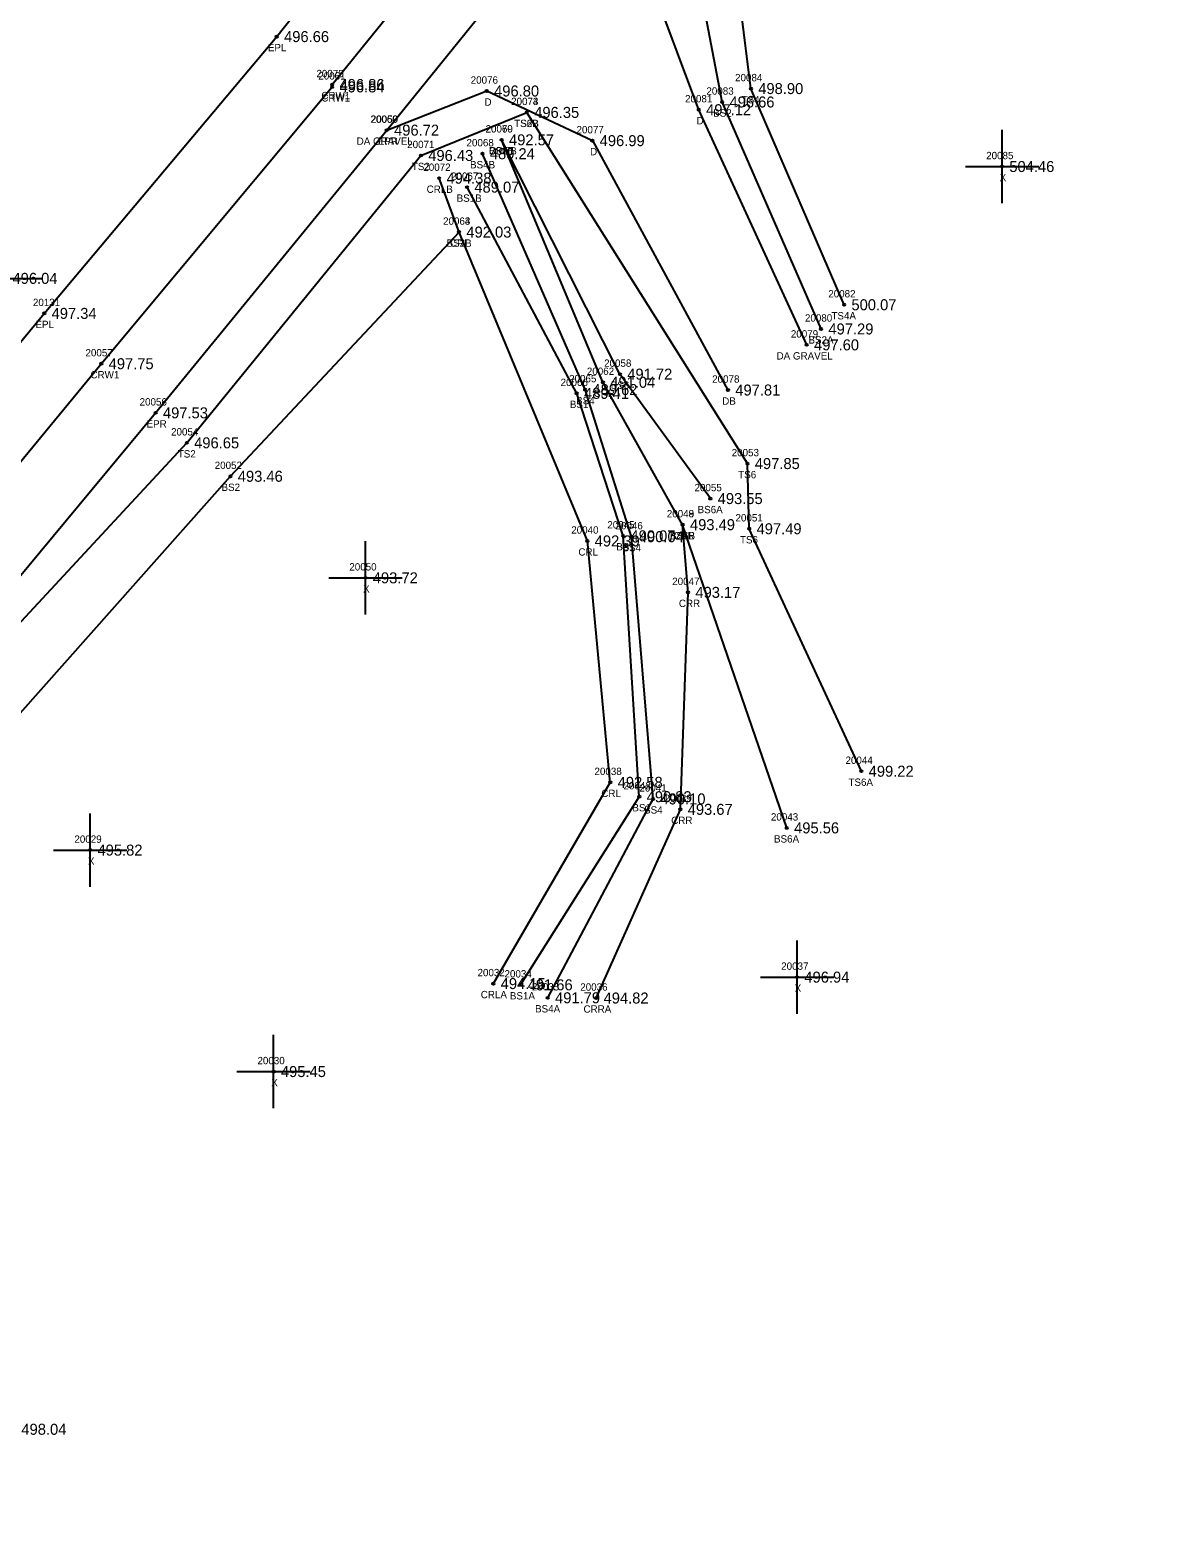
# Model space of a CAD drawing. Extents: x 1649406 to 1650436, y 896752 to 898178.
# Drawn here: x 1649581.2 to 1649733.9, y 896790.3 to 896995.9 of the extents above; entities that cross this region are included whole.
import ezdxf

# ---------------------------------------------------------------- set-up
doc = ezdxf.new("R2010")
doc.units = 0
for name, color, linetype in [('RD_DTM_BkLn1', 7, 'Continuous'), ('RD_DTM_BkLn2', 7, 'Continuous'), ('RD_DTM_BkLn_txCode', 7, 'Continuous'), ('RD_EX_Driveway', 7, 'Continuous'), ('RD_EX_Driveway_txCode', 7, 'Continuous'), ('RD_EX_H2O', 7, 'Continuous'), ('RD_EX_H2O_txCode', 7, 'Continuous'), ('RD_EX_Misc', 7, 'Continuous'), ('RD_EX_Misc_txCode', 7, 'Continuous'), ('RD_EX_Road', 7, 'Continuous'), ('RD_EX_Road_txCode', 7, 'Continuous'), ('RD_EX_TX_Driveway_ELEV', 7, 'Continuous'), ('RD_EX_TX_H2O_ELEV', 7, 'Continuous'), ('RD_EX_TX_Misc_ELEV', 7, 'Continuous'), ('RD_EX_TX_Road_ELEV', 7, 'Continuous'), ('RD_HC_Survey_ELEV', 7, 'Continuous'), ('RD_HC_Survey_txCode', 7, 'Continuous'), ('RD_SMD_Locator', 7, 'Continuous')]:
    doc.layers.add(name, color=color, linetype=linetype)

msp = doc.modelspace()

# ---------------------------------------------------------------- linework, layer by layer
at = {"layer": 'RD_DTM_BkLn1'}
msp.add_lwpolyline([(1649466.79, 896799.14), (1649494.97, 896834.25), (1649557.53, 896909.97), (1649590.88, 896950.41), (1649622.36, 896988.16), (1649622.36, 896988.48), (1649654.33, 897027.92), (1649685.38, 897067.52), (1649715.96, 897107.48), (1649743.64, 897146.32), (1649771.01, 897187.23), (1649797.64, 897230.08), (1649820.89, 897273.98), (1649842.91, 897321.22), (1649862.74, 897368.05), (1649877.08, 897408.66)], dxfattribs=at)
at = {"layer": 'RD_DTM_BkLn2'}
msp.add_line((1649684.35, 896887.11), (1649670.15, 896928.46), dxfattribs=at)
for points in [[(1649689.03, 896955.15), (1649675.54, 896986.1), (1649671.09, 897009.54), (1649678.93, 897030.09), (1649699.37, 897056.41), (1649730.7, 897097.01), (1649758.94, 897137.57), (1649785.6, 897178.21), (1649814.8, 897219.5), (1649846.42, 897264.34)], [(1649692.17, 896958.45), (1649679.46, 896987.93), (1649676.76, 897009.49), (1649682.34, 897025.02), (1649708.77, 897048.86), (1649742.68, 897086.45), (1649767.3, 897132.79), (1649789.94, 897176.61), (1649819.17, 897217.64), (1649850.28, 897262.86)], [(1649477.28, 896790.29), (1649506.04, 896824.84), (1649536.41, 896861.97), (1649567.77, 896902.18), (1649602.54, 896939.62), (1649634.46, 896978.81), (1649648.91, 896984.68)], [(1649694.52, 896894.84), (1649679.23, 896927.9), (1649678.99, 896936.79), (1649648.91, 896984.68)], [(1649673.93, 896932.02), (1649661.6, 896948.99), (1649645.47, 896980.94)], [(1649651.75, 896863.94), (1649666.13, 896891.06), (1649663.18, 896926.82), (1649656.85, 896946.88), (1649642.86, 896979.05)], [(1649648.02, 896865.71), (1649664.24, 896891.36), (1649662.04, 896926.94), (1649655.71, 896946.37), (1649640.75, 896974.49)], [(1649560.5, 896880.33), (1649573.3, 896895.47), (1649608.49, 896935.06), (1649639.66, 896968.36)]]:
    msp.add_lwpolyline(points, dxfattribs=at)
at = {"layer": 'RD_EX_Driveway'}
for points in [[(1649687.07, 896952.98), (1649672.35, 896985.05), (1649663.5, 897008.75), (1649667.92, 897029.33)], [(1649629.8, 896982.26), (1649643.44, 896987.6), (1649657.84, 896980.83), (1649676.33, 896946.82)]]:
    msp.add_lwpolyline(points, dxfattribs=at)
at = {"layer": 'RD_EX_H2O'}
for points in [[(1649658.37, 896863.91), (1649669.84, 896889.64), (1649670.89, 896919.23), (1649670.15, 896928.46), (1649659.28, 896947.88), (1649645.47, 896980.94)], [(1649644.34, 896865.88), (1649660.29, 896893.32), (1649657.16, 896926.24), (1649639.66, 896968.36), (1649636.95, 896975.71)]]:
    msp.add_lwpolyline(points, dxfattribs=at)
at = {"layer": 'RD_EX_Misc'}
for p, q in [((1649713.7, 896972.3), (1649713.7, 896982.3)), ((1649708.7, 896977.3), (1649718.7, 896977.3)), ((1649572.77, 896962.05), (1649582.77, 896962.05)), ((1649626.9, 896916.21), (1649626.9, 896926.21)), ((1649621.9, 896921.21), (1649631.9, 896921.21)), ((1649589.36, 896879.08), (1649589.36, 896889.08)), ((1649584.36, 896884.08), (1649594.36, 896884.08)), ((1649685.75, 896861.76), (1649685.75, 896871.76)), ((1649680.75, 896866.76), (1649690.75, 896866.76)), ((1649614.37, 896848.88), (1649614.37, 896858.88)), ((1649609.37, 896853.88), (1649619.37, 896853.88))]:
    msp.add_line(p, q, dxfattribs=at)
at = {"layer": 'RD_EX_Road'}
for points in [[(1649459.38, 896805.71), (1649486.55, 896839.62), (1649513.65, 896873.34), (1649538.22, 896902.56), (1649549.43, 896916.62), (1649583.1, 896957.27), (1649614.8, 896995.02), (1649647.06, 897035.69), (1649677.62, 897074.51), (1649708.33, 897114.44), (1649735.5, 897151.61), (1649762.11, 897192.19), (1649788.21, 897235.29), (1649812.17, 897279.73), (1649834.32, 897326.54), (1649852.94, 897371.82), (1649867.51, 897411.96)], [(1649474.75, 896792.65), (1649502.78, 896827.35), (1649565.2, 896903.92), (1649598.28, 896943.71), (1649629.8, 896982.26), (1649667.92, 897029.33), (1649693.13, 897061.44), (1649723.58, 897101.84), (1649752.37, 897141.09), (1649779.72, 897182.3), (1649806.12, 897225.84), (1649830.13, 897270.79), (1649852.39, 897317.43), (1649871.98, 897364.35), (1649886.55, 897406.09)]]:
    msp.add_lwpolyline(points, dxfattribs=at)
at = {"layer": 'RD_SMD_Locator'}
for centre in [(1649614.8, 896995.02), (1649622.36, 896988.48), (1649622.36, 896988.16), (1649643.44, 896987.6), (1649679.46, 896987.93), (1649648.91, 896984.68), (1649648.91, 896984.68), (1649672.35, 896985.05), (1649675.54, 896986.1), (1649629.8, 896982.26), (1649629.8, 896982.26), (1649645.47, 896980.94), (1649645.47, 896980.94), (1649657.84, 896980.83), (1649634.46, 896978.81), (1649642.86, 896979.05), (1649713.7, 896977.3), (1649636.95, 896975.71), (1649640.75, 896974.49), (1649639.66, 896968.36), (1649639.66, 896968.36), (1649692.17, 896958.45), (1649583.1, 896957.27), (1649689.03, 896955.15), (1649687.07, 896952.98), (1649590.88, 896950.41), (1649659.28, 896947.88), (1649661.6, 896948.99), (1649655.71, 896946.37), (1649656.85, 896946.88), (1649676.33, 896946.82), (1649598.28, 896943.71), (1649602.54, 896939.62), (1649608.49, 896935.06), (1649678.99, 896936.79), (1649673.93, 896932.02), (1649662.04, 896926.94), (1649663.18, 896926.82), (1649670.15, 896928.46), (1649670.15, 896928.46), (1649679.23, 896927.9), (1649657.16, 896926.24), (1649626.9, 896921.21), (1649670.89, 896919.23), (1649694.52, 896894.84), (1649660.29, 896893.32), (1649664.24, 896891.36), (1649666.13, 896891.06), (1649669.84, 896889.64), (1649684.35, 896887.11), (1649589.36, 896884.08), (1649644.34, 896865.88), (1649648.02, 896865.71), (1649685.75, 896866.76), (1649651.75, 896863.94), (1649658.37, 896863.91), (1649614.37, 896853.88)]:
    msp.add_circle(centre, 0.15, dxfattribs=at)

# ---------------------------------------------------------------- texts
at = {"layer": 'RD_DTM_BkLn_txCode'}
for s, p in [('20084', (1649677.3, 896988.93)), ('20073', (1649646.76, 896985.68)), ('20074', (1649646.76, 896985.68)), ('20083', (1649673.39, 896987.1)), ('TS4', (1649678.21, 896985.93)), ('BS2', (1649674.32, 896984.1)), ('20070', (1649643.27, 896981.94)), ('TS6B', (1649647.17, 896982.68)), ('TS2B', (1649647.2, 896982.68)), ('20071', (1649632.59, 896979.81)), ('20068', (1649640.68, 896980.05)), ('BS6B', (1649643.74, 896978.94)), ('TS2', (1649633.22, 896976.81)), ('20067', (1649638.57, 896975.49)), ('BS4B', (1649641.16, 896977.05)), ('BS1B', (1649639.33, 896972.49)), ('20063', (1649637.48, 896969.36)), ('BS2B', (1649637.96, 896966.36)), ('20082', (1649690.01, 896959.45)), ('20080', (1649686.83, 896956.15)), ('TS4A', (1649690.44, 896956.45)), ('BS2A', (1649687.31, 896953.15)), ('20058', (1649659.44, 896949.99)), ('20066', (1649653.51, 896947.37)), ('20065', (1649654.67, 896947.88)), ('BS6', (1649660.35, 896946.99)), ('BS1', (1649654.77, 896944.37)), ('BS4', (1649655.62, 896944.88)), ('20054', (1649600.39, 896940.62)), ('TS2', (1649601.3, 896937.62)), ('20052', (1649606.34, 896936.06)), ('20053', (1649676.84, 896937.79)), ('TS6', (1649677.73, 896934.79)), ('BS2', (1649607.27, 896933.06)), ('20055', (1649671.77, 896933.02)), ('BS6A', (1649672.19, 896930.02)), ('20045', (1649659.88, 896927.94)), ('20046', (1649661, 896927.82)), ('20049', (1649667.99, 896929.46)), ('20051', (1649677.36, 896928.9)), ('BS6B', (1649668.43, 896926.46)), ('TS6', (1649677.97, 896925.9)), ('BS1', (1649661.1, 896924.94)), ('BS4', (1649661.95, 896924.82)), ('20044', (1649692.36, 896895.84)), ('TS6A', (1649692.76, 896892.84)), ('20042', (1649662.09, 896892.36)), ('20041', (1649664.26, 896892.06)), ('BS1', (1649663.3, 896889.36)), ('BS4', (1649664.9, 896889.06)), ('20043', (1649682.19, 896888.11)), ('BS6A', (1649682.61, 896885.11)), ('20034', (1649645.86, 896866.71)), ('20035', (1649649.59, 896864.94)), ('BS1A', (1649646.59, 896863.71)), ('BS4A', (1649650.03, 896861.94))]:
    msp.add_text(s, height=1, dxfattribs=at).set_placement(p)
at = {"layer": 'RD_EX_Driveway_txCode'}
for s, p in [('20076', (1649641.25, 896988.6)), ('D', (1649643.13, 896985.6)), ('20081', (1649670.48, 896986.05)), ('20060', (1649627.58, 896983.26)), ('20077', (1649655.68, 896981.83)), ('D', (1649672.04, 896983.05)), ('DA GRAVEL', (1649625.7, 896980.26)), ('D', (1649657.53, 896978.83)), ('20079', (1649684.91, 896953.98)), ('DA GRAVEL', (1649682.96, 896950.98)), ('20078', (1649674.18, 896947.82)), ('DB', (1649675.55, 896944.82))]:
    msp.add_text(s, height=1, dxfattribs=at).set_placement(p)
at = {"layer": 'RD_EX_H2O_txCode'}
for s, p in [('20069', (1649643.28, 896981.94)), ('CRRB', (1649643.74, 896978.94)), ('20072', (1649634.79, 896976.71)), ('CRLB', (1649635.24, 896973.71)), ('20064', (1649637.48, 896969.36)), ('CRL', (1649638.43, 896966.36)), ('20062', (1649657.09, 896948.88)), ('CRR', (1649658.02, 896945.88)), ('20048', (1649667.99, 896929.46)), ('20040', (1649654.96, 896927.24)), ('CRR', (1649668.9, 896926.46)), ('CRL', (1649655.93, 896924.24)), ('20047', (1649668.73, 896920.23)), ('CRR', (1649669.64, 896917.23)), ('20038', (1649658.13, 896894.32)), ('CRL', (1649659.06, 896891.32)), ('20039', (1649667.68, 896890.64)), ('CRR', (1649668.59, 896887.64)), ('20032', (1649642.18, 896866.88)), ('20036', (1649656.19, 896864.91)), ('CRLA', (1649642.62, 896863.88)), ('CRRA', (1649656.63, 896861.91))]:
    msp.add_text(s, height=1, dxfattribs=at).set_placement(p)
at = {"layer": 'RD_EX_Misc_txCode'}
for s, p in [('20085', (1649711.54, 896978.3)), ('X', (1649713.38, 896975.3)), ('20050', (1649624.7, 896922.21)), ('X', (1649626.58, 896919.21)), ('20029', (1649587.21, 896885.08)), ('X', (1649589.05, 896882.08)), ('20037', (1649683.59, 896867.76)), ('X', (1649685.43, 896864.76)), ('20030', (1649612.17, 896854.88)), ('X', (1649614.05, 896851.88))]:
    msp.add_text(s, height=1, dxfattribs=at).set_placement(p)
at = {"layer": 'RD_EX_Road_txCode'}
for s, p in [('EPL', (1649613.59, 896993.02)), ('20059', (1649627.64, 896983.26)), ('EPR', (1649628.57, 896980.26)), ('20131', (1649581.55, 896958.27)), ('EPL', (1649581.9, 896955.27)), ('20056', (1649596.1, 896944.71)), ('EPR', (1649597.05, 896941.71))]:
    msp.add_text(s, height=1, dxfattribs=at).set_placement(p)
at = {"layer": 'RD_EX_TX_Driveway_ELEV'}
for s, p in [('496.80', (1649644.44, 896986.85)), ('497.12', (1649673.35, 896984.3)), ('496.72', (1649630.8, 896981.51)), ('496.99', (1649658.84, 896980.08)), ('497.60', (1649688.07, 896952.23)), ('497.81', (1649677.33, 896946.07))]:
    msp.add_text(s, height=1.5, dxfattribs=at).set_placement(p)
at = {"layer": 'RD_EX_TX_H2O_ELEV'}
for s, p in [('492.57', (1649646.47, 896980.19)), ('494.38', (1649637.95, 896974.96)), ('492.03', (1649640.66, 896967.61)), ('491.04', (1649660.28, 896947.13)), ('493.49', (1649671.15, 896927.71)), ('492.39', (1649658.16, 896925.49)), ('493.17', (1649671.89, 896918.48)), ('492.58', (1649661.29, 896892.57)), ('493.67', (1649670.84, 896888.89)), ('494.15', (1649645.34, 896865.13)), ('494.82', (1649659.37, 896863.16))]:
    msp.add_text(s, height=1.5, dxfattribs=at).set_placement(p)
at = {"layer": 'RD_EX_TX_Misc_ELEV'}
for s, p in [('498.90', (1649680.46, 896987.18)), ('496.66', (1649676.54, 896985.35)), ('496.35', (1649649.91, 896983.93)), ('496.35', (1649649.91, 896983.93)), ('492.57', (1649646.47, 896980.19)), ('496.43', (1649635.46, 896978.06)), ('489.24', (1649643.86, 896978.3)), ('504.46', (1649714.7, 896976.55)), ('489.07', (1649641.75, 896973.74)), ('492.03', (1649640.66, 896967.61)), ('496.04', (1649578.77, 896961.3)), ('500.07', (1649693.17, 896957.7)), ('497.29', (1649690.03, 896954.4)), ('491.72', (1649662.6, 896948.24)), ('489.62', (1649657.85, 896946.13)), ('489.41', (1649656.71, 896945.62)), ('496.65', (1649603.54, 896938.87)), ('497.85', (1649679.99, 896936.04)), ('493.46', (1649609.49, 896934.31)), ('493.55', (1649674.93, 896931.27)), ('493.49', (1649671.15, 896927.71)), ('490.07', (1649663.04, 896926.19)), ('490.04', (1649664.18, 896926.07)), ('497.49', (1649680.23, 896927.15)), ('493.72', (1649627.9, 896920.46)), ('499.22', (1649695.52, 896894.09)), ('490.83', (1649665.24, 896890.61)), ('490.10', (1649667.13, 896890.31)), ('495.56', (1649685.35, 896886.36)), ('495.82', (1649590.36, 896883.33)), ('496.94', (1649686.75, 896866.01)), ('491.66', (1649649.02, 896864.96)), ('491.79', (1649652.75, 896863.19)), ('495.45', (1649615.37, 896853.13)), ('498.04', (1649579.98, 896804.35))]:
    msp.add_text(s, height=1.5, dxfattribs=at).set_placement(p)
at = {"layer": 'RD_EX_TX_Road_ELEV'}
for s, p in [('496.66', (1649615.8, 896994.27)), ('496.72', (1649630.8, 896981.51)), ('497.34', (1649584.1, 896956.52)), ('497.53', (1649599.28, 896942.96))]:
    msp.add_text(s, height=1.5, dxfattribs=at).set_placement(p)
at = {"layer": 'RD_HC_Survey_ELEV'}
for s, p in [('496.86', (1649623.36, 896987.73)), ('496.84', (1649623.36, 896987.41)), ('497.75', (1649591.88, 896949.66))]:
    msp.add_text(s, height=1.5, dxfattribs=at).set_placement(p)
at = {"layer": 'RD_HC_Survey_txCode'}
for s, p in [('20075', (1649620.21, 896989.48)), ('20061', (1649620.47, 896989.16)), ('CRW1', (1649620.88, 896986.48)), ('CRW1', (1649620.88, 896986.16)), ('20057', (1649588.72, 896951.41)), ('CRW1', (1649589.4, 896948.41))]:
    msp.add_text(s, height=1, dxfattribs=at).set_placement(p)

doc.saveas('drawing.dxf')
